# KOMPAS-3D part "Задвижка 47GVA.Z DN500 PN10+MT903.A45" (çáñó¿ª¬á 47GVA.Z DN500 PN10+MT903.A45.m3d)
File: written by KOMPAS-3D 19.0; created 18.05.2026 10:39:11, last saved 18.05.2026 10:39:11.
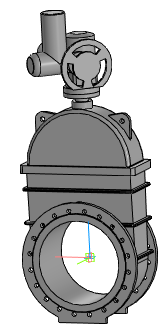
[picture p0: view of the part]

Document properties: Автор: Энергия; Полное имя файла: ..\Задвижка 47GVA.Z DN350_DN1200+MT903.A\Задвижка 47GVA.Z DN500 PN10+MT903.A45.a3d

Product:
- Part/product: Задвижка 47GVA.Z DN500 PN10+MT903.A45
    Масса: 1152.78
  - Body: Электропривод МТ903.А45 без блока управления
      Масса: 175.721
  - Body: Задвижка 47GVA.Z DN500 PN10 без исполнит. мех.
      Масса: 977.056

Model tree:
1. Операция без истории:1
2. Операция без истории:2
